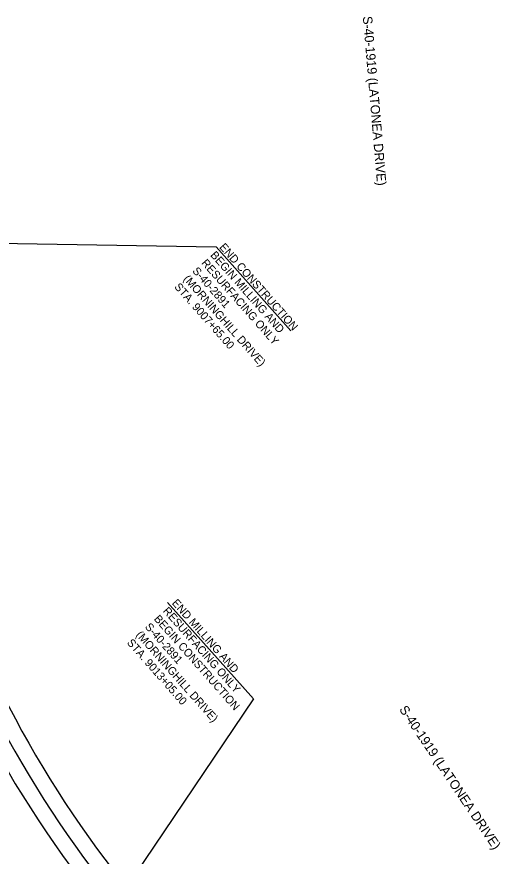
# Model space of a CAD drawing. Extents: x 1966090 to 1975830, y 788086 to 801233.
# Drawn here: x 1969648 to 1970010, y 798102 to 798731 of the extents above; entities that cross this region are included whole.
import ezdxf

# ---------------------------------------------------------------- set-up
doc = ezdxf.new("R2010")
doc.units = 0
for name, color, linetype in [('RD_EX_Driveway_txCode', 7, 'Continuous'), ('RD_EX_SU_H2O', 7, 'Continuous'), ('RD_EX_Survey_Limits', 7, 'Continuous'), ('RD_Sketch6', 7, 'Continuous'), ('RD_Sketch8', 7, 'Continuous')]:
    doc.layers.add(name, color=color, linetype=linetype)

msp = doc.modelspace()

# ---------------------------------------------------------------- linework, layer by layer
at = {"layer": 'RD_EX_Survey_Limits'}
msp.add_arc((1970357.34, 798584.73), 817.94, 194.81615, 218.48003, dxfattribs=at)
at = {"layer": 'RD_Sketch6'}
for p, q in [((1969522.64, 798563.33), (1969797.07, 798558.42)), ((1969853.16, 798495.6), (1969797.07, 798558.42)), ((1969825.05, 798219.92), (1969760.73, 798291.95)), ((1969825.05, 798219.92), (1969722.78, 798068.54))]:
    msp.add_line(p, q, dxfattribs=at)
at = {"layer": 'RD_Sketch8'}
for radius in [805.94, 829.94]:
    msp.add_arc((1970357.34, 798584.73), radius, 194.81615, 218.48003, dxfattribs=at)

# ---------------------------------------------------------------- texts
at = {"layer": 'RD_EX_Driveway_txCode'}
msp.add_text('S-40-1919 (LATONEA DRIVE)', height=7, rotation=274.85982, dxfattribs=at).set_placement((1969906.99, 798731.11))
at = {"layer": 'RD_EX_SU_H2O'}
msp.add_text('S-40-1919 (LATONEA DRIVE)', height=7, rotation=303.93309, dxfattribs=at).set_placement((1969934.01, 798211.94))
at = {"layer": 'RD_Sketch6'}
for s, height, p in [('END CONSTRUCTION', 5.9996, (1969799.1, 798558.06)), ('BEGIN MILLING AND ', 5.9996, (1969792.35, 798552.1)), ('RESURFACING ONLY', 5.9996, (1969785.6, 798546.15)), ('S-40-2891', 6, (1969778.86, 798540.19)), ('(MORNINGHILL DRIVE)', 5.9996, (1969772.11, 798534.24)), ('STA. 9007+65.00', 5.9996, (1969765.36, 798528.28)), ('END MILLING AND', 5.9996, (1969763.55, 798291.41)), ('BEGIN CONSTRUCTION', 5.9996, (1969750.05, 798279.5)), ('RESURFACING ONLY', 5.9996, (1969756.8, 798285.46)), ('S-40-2891', 6, (1969743.3, 798273.55)), ('(MORNINGHILL DRIVE)', 5.9996, (1969736.56, 798267.59)), ('STA. 9013+05.00', 5.9996, (1969729.81, 798261.64))]:
    msp.add_text(s, height=height, rotation=311.42867, dxfattribs=at).set_placement(p)

doc.saveas('drawing.dxf')
